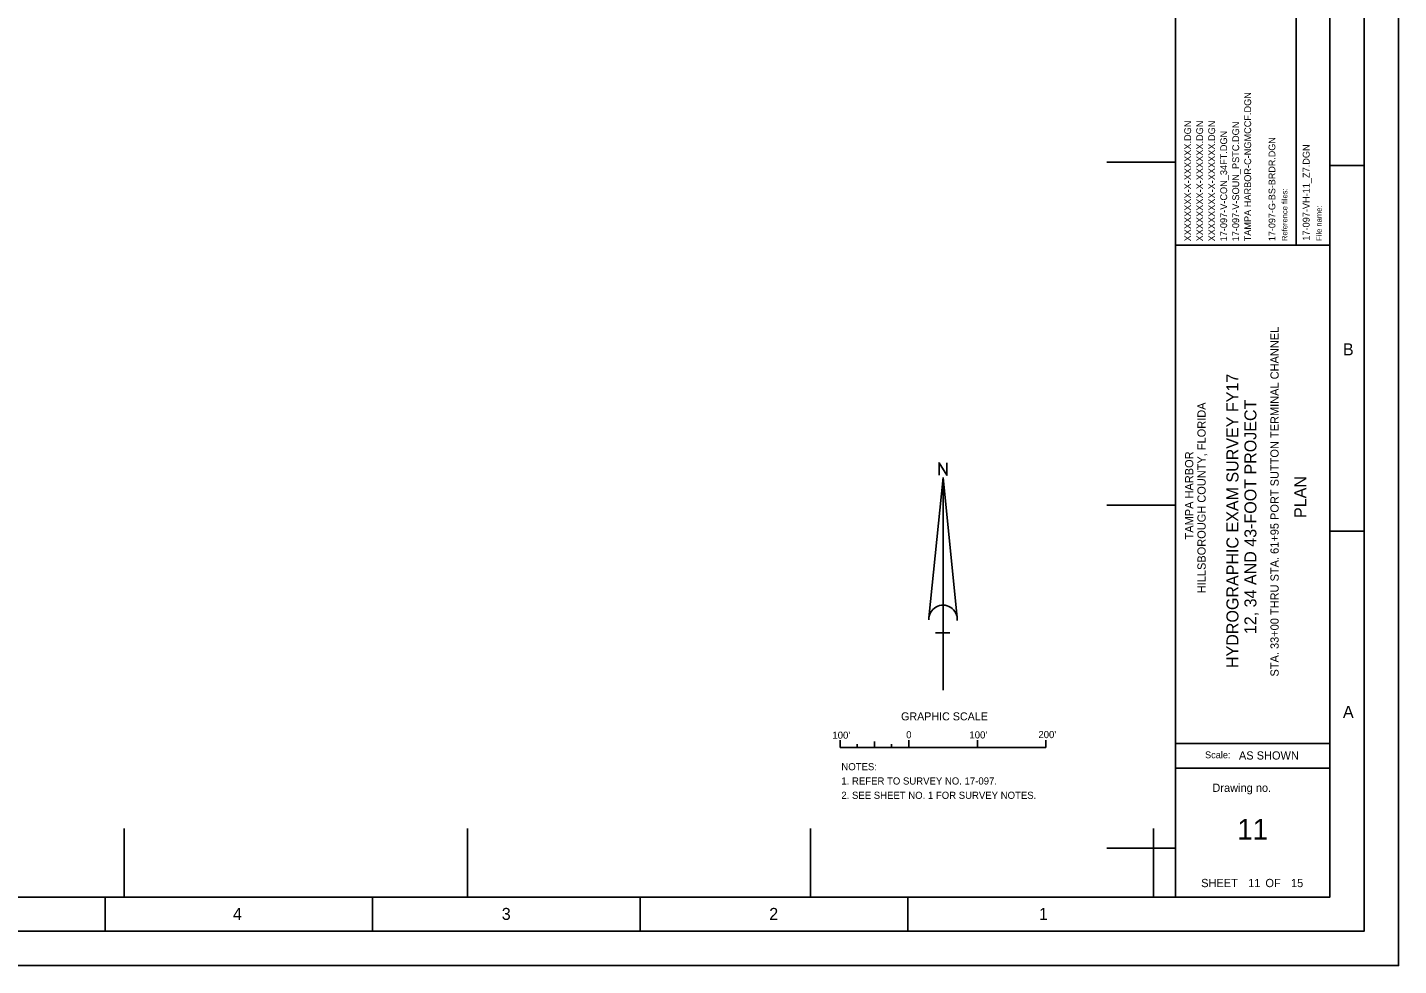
# Model space of a CAD drawing. Extents: x 520957 to 525357, y 1296329 to 1299729.
# Drawn here: x 523359 to 525357, y 1296329 to 1297697 of the extents above; entities that cross this region are included whole.
import ezdxf

# ---------------------------------------------------------------- set-up
doc = ezdxf.new("R2010")
doc.units = 0
for name, color, linetype in [('G-ANNO-NPLT', 7, 'Continuous'), ('G-ANNO-TEXT-DRWG', 7, 'Continuous'), ('G-ANNO-TEXT-PROJ', 7, 'Continuous'), ('G-ANNO-TEXT-TTLB', 7, 'Continuous'), ('G-ANNO-TTLB', 7, 'Continuous'), ('V-ANNO-NOTE', 7, 'Continuous'), ('V-ANNO-SYMB', 7, 'Continuous'), ('V-TOPO-COOR-STAT', 7, 'Continuous')]:
    doc.layers.add(name, color=color, linetype=linetype)

msp = doc.modelspace()

# ---------------------------------------------------------------- linework, layer by layer
at = {"layer": 'G-ANNO-NPLT'}
msp.add_lwpolyline([(520957.1, 1299728.6), (525357, 1299728.6), (525357, 1296328.6), (520957.1, 1296328.6)], close=True, dxfattribs=at)
msp.add_lwpolyline([(525357.2, 1296378.6), (525357.2, 1296328.6), (525307.2, 1296328.6)], dxfattribs=at)
at = {"layer": 'G-ANNO-TTLB'}
for p, q in [((525032, 1299628.6), (525032, 1296428.6)), ((525207.7, 1297730.7), (525207.7, 1297379.3)), ((525307, 1297495.2), (525257, 1297495.2)), ((525032, 1297379.3), (525257, 1297379.3)), ((525307, 1296961.9), (525257, 1296961.9)), ((525032, 1296652.3), (525257, 1296652.3)), ((525032, 1296616.6), (525257, 1296616.6)), ((523472, 1296378.6), (523472, 1296428.6)), ((523862, 1296378.6), (523862, 1296428.6)), ((524252, 1296378.6), (524252, 1296428.6)), ((524642, 1296378.6), (524642, 1296428.6))]:
    msp.add_line(p, q, dxfattribs=at)
for points in [[(521007.1, 1296378.6), (525307, 1296378.6), (525307, 1299678.6), (521007.1, 1299678.6)], [(525257, 1299628.6), (521132.1, 1299628.6), (521132.1, 1296428.6), (525257, 1296428.6)]]:
    msp.add_lwpolyline(points, close=True, dxfattribs=at)
at = {"layer": 'V-ANNO-NOTE'}
for p, q in [((524543.3, 1296646.6), (524543.3, 1296657.1)), ((524593.3, 1296646.6), (524593.3, 1296655.2)), ((524643.3, 1296646.6), (524643.3, 1296657.1)), ((524643.3, 1296646.6), (524643.3, 1296657.1)), ((524743.3, 1296646.6), (524743.3, 1296657.1)), ((524843.3, 1296646.6), (524843.3, 1296657.1)), ((524543.3, 1296646.6), (524843.3, 1296646.6)), ((524568.3, 1296646.6), (524568.3, 1296651.4)), ((524618.3, 1296646.6), (524618.3, 1296651.4)), ((524643.3, 1296646.6), (524643.3, 1296651.6))]:
    msp.add_line(p, q, dxfattribs=at)
at = {"layer": 'V-ANNO-SYMB'}
for p, q in [((524672.7, 1296835.6), (524693.3, 1297040.4)), ((524693.3, 1296730.1), (524693.3, 1297040.4)), ((524713.9, 1296835.6), (524693.3, 1297040.4)), ((524703.1, 1296813.9), (524682.4, 1296813.9))]:
    msp.add_line(p, q, dxfattribs=at)
msp.add_lwpolyline([(524687.6, 1297043.7), (524687.6, 1297061.8), (524698.9, 1297043.7), (524698.9, 1297061.8)], dxfattribs=at)
msp.add_arc((524693.3, 1296833.5), 20.7, 355.2984, 182.0673, dxfattribs=at)
at = {"layer": 'V-TOPO-COOR-STAT'}
for p, q in [((525032, 1297500), (524932, 1297500)), ((525032, 1297000), (524932, 1297000)), ((523500, 1296428.6), (523500, 1296528.6)), ((524000, 1296428.6), (524000, 1296528.6)), ((524500, 1296428.6), (524500, 1296528.6)), ((525000, 1296428.6), (525000, 1296528.6)), ((525032, 1296500), (524932, 1296500))]:
    msp.add_line(p, q, dxfattribs=at)

# ---------------------------------------------------------------- texts
at = {"layer": 'G-ANNO-TEXT-DRWG'}
for s, height, p in [('TAMPA HARBOR-C-NGMCCF.DGN', 10, (525142.3, 1297384.7)), ('XXXXXXXX-X-XXXXXX.DGN', 10, (525054.8, 1297384.7)), ('XXXXXXXX-X-XXXXXX.DGN', 10, (525072.3, 1297384.7)), ('XXXXXXXX-X-XXXXXX.DGN', 10, (525089.8, 1297384.7)), ('17-097-V-SOUN_PSTC.DGN', 10, (525124.8, 1297384.7)), ('17-097-V-CON_34FT.DGN', 10, (525107.3, 1297384.7)), ('17-097-VH-11_Z7.DGN', 10, (525227.5, 1297385.7)), ('STA. 33+00 THRU STA. 61+95 PORT SUTTON TERMINAL CHANNEL', 12, (525182.4, 1296750.1)), ('PLAN', 17.5, (525222.6, 1296981.3))]:
    msp.add_text(s, height=height, rotation=90, dxfattribs=at).set_placement(p)
for s, height, p in [('11', 30, (525122.2, 1296512.4)), (' 11          15', 12, (525133.5, 1296443))]:
    msp.add_text(s, height=height, dxfattribs=at).set_placement(p)
at = {"layer": 'G-ANNO-TEXT-PROJ'}
for s, height, p in [('17-097-G-BS-BRDR.DGN', 9.8, (525177.5, 1297385.1)), ('HYDROGRAPHIC EXAM SURVEY FY17', 17.5, (525123.8, 1296762.5)), ('HILLSBOROUGH COUNTY, FLORIDA', 12, (525076, 1296871.6)), ('12, 34 AND 43-FOOT PROJECT', 17.5, (525150, 1296811.9)), ('TAMPA HARBOR', 12, (525058, 1296950))]:
    msp.add_text(s, height=height, rotation=90, dxfattribs=at).set_placement(p)
at = {"layer": 'G-ANNO-TEXT-TTLB'}
for s, p in [('Reference files:', (525195.1, 1297385.2)), ('File name:', (525245.1, 1297385.4))]:
    msp.add_text(s, height=8, rotation=90, dxfattribs=at).set_placement(p)
for s, height, p in [('Scale:', 10, (525075.1, 1296630.9)), ('AS SHOWN', 12, (525124.5, 1296629)), ('Drawing no.', 12, (525085.8, 1296581.9)), ('SHEET         OF', 12, (525069.5, 1296443))]:
    msp.add_text(s, height=height, dxfattribs=at).set_placement(p)
at = {"layer": 'G-ANNO-TTLB'}
for s, p in [('B', (525276.1, 1297218.5)), ('A', (525276.1, 1296689.8)), ('4', (523658.4, 1296395.2)), ('3', (524050.2, 1296395.2)), ('2', (524440, 1296395.2)), ('1', (524833.1, 1296395.2))]:
    msp.add_text(s, height=17.5, dxfattribs=at).set_placement(p)
at = {"layer": 'V-ANNO-NOTE'}
for s, height, p in [('GRAPHIC SCALE', 11.666, (524632.1, 1296686.2)), ("100'", 10.42, (524532, 1296659.4)), ('0', 10.4, (524639.6, 1296660.1)), ("100'", 10.42, (524731.7, 1296659.8)), ("200'", 10.42, (524832.2, 1296660.3)), ('NOTES:', 10.42, (524545.1, 1296613.4)), ('1. REFER TO SURVEY NO. 17-097.', 10.416, (524545.1, 1296592.6)), ('2. SEE SHEET NO. 1 FOR SURVEY NOTES.', 10.416, (524545.1, 1296571.7))]:
    msp.add_text(s, height=height, dxfattribs=at).set_placement(p)

doc.saveas('drawing.dxf')
